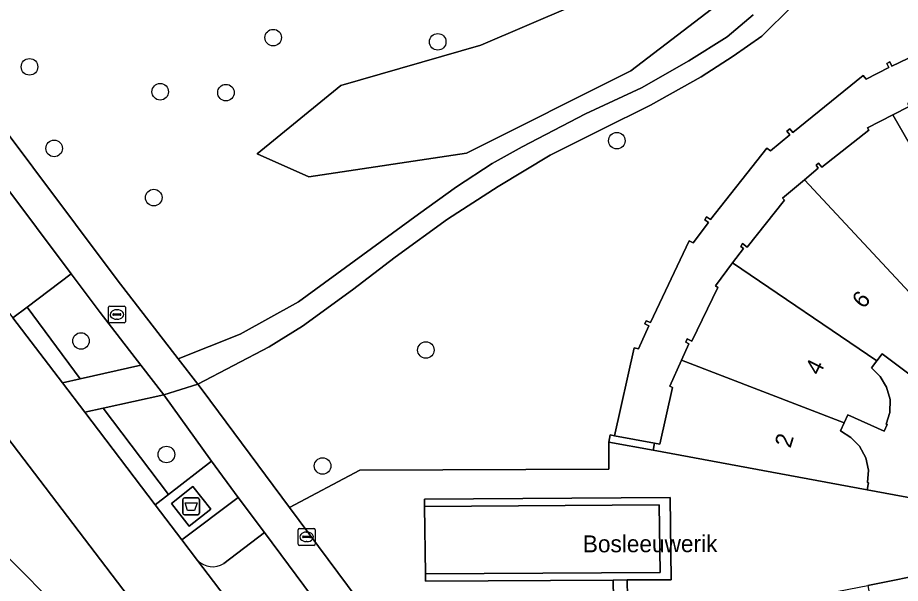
# Model space of a CAD drawing. Extents: x 156661 to 157576, y 383570 to 384425.
# Drawn here: x 156984.6 to 157036.8, y 384097.3 to 384130.7 of the extents above; entities that cross this region are included whole.
import ezdxf

# ---------------------------------------------------------------- set-up
doc = ezdxf.new("R2010")
doc.units = 0
for name, color, linetype in [('IMGEO_Afval_apart_plaats', 7, 'Continuous'), ('IMGEO_Berm_groen', 7, 'Continuous'), ('IMGEO_Berm_open', 7, 'Continuous'), ('IMGEO_Boom', 7, 'Continuous'), ('IMGEO_Brandkraan', 7, 'Continuous'), ('IMGEO_Erf', 7, 'Continuous'), ('IMGEO_Fietspad_gesloten', 7, 'Continuous'), ('IMGEO_Greppel_droge_sloot', 7, 'Continuous'), ('IMGEO_Groenvoorziening', 7, 'Continuous'), ('IMGEO_Kolk', 7, 'Continuous'), ('IMGEO_Muur', 7, 'Continuous'), ('IMGEO_Openbare_ruimte_label', 7, 'Continuous'), ('IMGEO_Pand', 7, 'Continuous'), ('IMGEO_Pand_nummerreeks', 7, 'Continuous'), ('IMGEO_Parkeervlak_open', 7, 'Continuous'), ('IMGEO_Rijbaan_lokaal_gesloten', 7, 'Continuous'), ('IMGEO_Rijbaan_lokaal_open', 7, 'Continuous'), ('IMGEO_Voetpad_gesloten', 7, 'Continuous'), ('IMGEO_Voetpad_halfverhard', 7, 'Continuous'), ('IMGEO_Voetpad_open', 7, 'Continuous')]:
    doc.layers.add(name, color=color, linetype=linetype)

msp = doc.modelspace()

# ---------------------------------------------------------------- linework, layer by layer
at = {"layer": 'IMGEO_Afval_apart_plaats'}
for p, q in [((156994.354, 384101.414), (156994.354, 384102.214)), ((156994.354, 384102.214), (156994.354, 384101.414)), ((156994.454, 384102.314), (156995.244, 384102.314)), ((156995.244, 384102.314), (156994.454, 384102.314)), ((156995.344, 384102.214), (156995.344, 384101.414)), ((156995.344, 384101.414), (156995.344, 384102.214)), ((156995.244, 384101.314), (156994.454, 384101.314)), ((156994.454, 384101.314), (156995.244, 384101.314))]:
    msp.add_line(p, q, dxfattribs=at)
msp.add_lwpolyline([(156994.497, 384102.028), (156995.201, 384102.028), (156995.052, 384101.558), (156994.646, 384101.558), (156994.497, 384102.028)], dxfattribs=at)
for centre, start, end in [((156994.454, 384102.214), 90, 180), ((156994.454, 384102.214), 90, 180), ((156995.244, 384102.214), 0, 90), ((156995.244, 384102.214), 360, 90), ((156994.454, 384101.414), 180, 270), ((156994.454, 384101.414), 180, 270), ((156995.244, 384101.414), 270, 0), ((156995.244, 384101.414), 270, 0)]:
    msp.add_arc(centre, 0.1, start, end, dxfattribs=at)
at = {"layer": 'IMGEO_Berm_groen'}
for points in [[(156989.479, 384113.271), (156987.764, 384115.552), (156985.156, 384113.579), (156988.303, 384109.35), (156991.886, 384110.152)], [(156993.23, 384108.41), (156989.647, 384107.62), (156993.506, 384102.511), (156996.047, 384104.484)]]:
    msp.add_lwpolyline(points, close=True, dxfattribs=at)
msp.add_lwpolyline([(156991.93, 384090.278), (156994.406, 384092.206), (156983.642, 384106.325)], dxfattribs=at)
msp.add_arc((156891.837, 384005.355), 131.265, 40.31264, 47.88862, dxfattribs=at)
at = {"layer": 'IMGEO_Berm_open'}
for points in [[(156985.156, 384113.579), (156984.323, 384112.949), (156987.249, 384109.103), (156988.303, 384109.35)], [(156989.647, 384107.62), (156988.566, 384107.372), (156992.723, 384101.907), (156993.506, 384102.511)]]:
    msp.add_lwpolyline(points, close=True, dxfattribs=at)
at = {"layer": 'IMGEO_Boom'}
for centre in [(156999.703, 384129.513), (157009.428, 384129.265), (156985.299, 384127.786), (156993.025, 384126.315), (156996.911, 384126.263), (157020.016, 384123.422), (156986.756, 384122.965), (156992.644, 384120.061), (156988.345, 384111.588), (157008.728, 384111.051), (156993.392, 384104.878), (157002.623, 384104.198)]:
    msp.add_circle(centre, 0.489, dxfattribs=at)
at = {"layer": 'IMGEO_Brandkraan'}
for p, q in [((156990.039, 384113.651), (156990.891, 384113.651)), ((156989.964, 384112.725), (156989.964, 384113.577)), ((156990.223, 384113.145), (156990.223, 384113.157)), ((156990.661, 384113.108), (156990.263, 384113.108)), ((156990.266, 384113.194), (156990.664, 384113.194)), ((156990.452, 384113.431), (156990.477, 384113.431)), ((156990.707, 384113.157), (156990.707, 384113.145)), ((156990.965, 384113.577), (156990.965, 384112.725)), ((156990.891, 384112.651), (156990.039, 384112.651)), ((156990.475, 384112.871), (156990.45, 384112.871))]:
    msp.add_line(p, q, dxfattribs=at)
for points in [[(156990.039, 384113.651), (156990.891, 384113.651)], [(156989.964, 384112.725), (156989.964, 384113.577)], [(156990.965, 384113.577), (156990.965, 384112.725)], [(156990.891, 384112.651), (156990.039, 384112.651)]]:
    msp.add_lwpolyline(points, dxfattribs=at)
for centre, radius, start, end in [((156990.041, 384113.575), 0.0765, 91.552, 178.448), ((156990.041, 384113.575), 0.0765, 91.552, 178.448), ((156990.889, 384113.575), 0.0765, 1.552, 88.448), ((156990.889, 384113.575), 0.0765, 1.552, 88.448), ((156990.263, 384113.154), 0.0403, 85.8775, 175.7526), ((156990.26, 384113.144), 0.0366, 178.938, 274.7102), ((156990.664, 384113.151), 0.043, 264.8664, 352.4533), ((156990.668, 384113.156), 0.0386, 1.7309, 96.639), ((156990.041, 384112.727), 0.0765, 181.552, 268.448), ((156990.041, 384112.727), 0.0765, 181.552, 268.448), ((156990.889, 384112.727), 0.0765, 271.552, 358.448), ((156990.889, 384112.727), 0.0765, 271.552, 358.448)]:
    msp.add_arc(centre, radius, start, end, dxfattribs=at)
for centre, major_axis, ratio, start_param, end_param in [((156990.451, 384113.151), (-0.387, 0.002), 0.722429, 4.712389, 7.853982), ((156990.476, 384113.151), (-0.39, 0.002), 0.717154, 1.570796, 4.712389)]:
    msp.add_ellipse(centre, major_axis=major_axis, ratio=ratio, start_param=start_param, end_param=end_param, dxfattribs=at)
at = {"layer": 'IMGEO_Erf'}
for points in [[(157041.118, 384130.156), (157036.279, 384127.836), (157036.154, 384128.079), (157035.969, 384127.983), (157036.093, 384127.743), (157034.746, 384127.057), (157034.572, 384127.271), (157030.415, 384123.905), (157030.234, 384124.118), (157030.072, 384123.98), (157030.247, 384123.775), (157029.094, 384122.813), (157028.877, 384122.984), (157025.551, 384118.755), (157025.324, 384118.924), (157025.217, 384118.753), (157025.434, 384118.592), (157024.534, 384117.386), (157024.285, 384117.503), (157022.003, 384112.671), (157021.75, 384112.785), (157021.666, 384112.595), (157021.913, 384112.485), (157021.294, 384111.118), (157021.03, 384111.176), (157019.882, 384105.99), (157022.239, 384105.555), (157022.552, 384105.497), (157023.303, 384108.845), (157023.154, 384108.912), (157023.841, 384110.452), (157024.273, 384111.42), (157024.086, 384111.515), (157024.163, 384111.705), (157024.455, 384111.565), (157025.984, 384114.749), (157025.846, 384114.853), (157026.859, 384116.199), (157027.498, 384117.048), (157027.336, 384117.178), (157027.45, 384117.345), (157027.713, 384117.136), (157029.919, 384119.902), (157029.814, 384120.027), (157031.102, 384121.115), (157031.914, 384121.8), (157031.788, 384121.968), (157031.944, 384122.1), (157032.139, 384121.853), (157034.906, 384124.041), (157034.832, 384124.186), (157036.336, 384124.956), (157037.285, 384125.441)], [(157037.593, 384109.417), (157035.706, 384110.832), (157035.386, 384110.419), (157035.065, 384110.006), (157035.581, 384109.483), (157035.958, 384108.858), (157036.172, 384108.119), (157036.157, 384107.369), (157035.944, 384106.666), (157035.999, 384106.642), (157035.824, 384106.264), (157033.667, 384107.221), (157033.449, 384106.75), (157033.23, 384106.279), (157033.85, 384105.885), (157034.357, 384105.36), (157034.731, 384104.688), (157034.884, 384103.953), (157034.834, 384103.221), (157034.893, 384103.21), (157034.816, 384102.793), (157038.761, 384102.061)], [(157038.769, 384097.919), (157034.843, 384097.129), (157034.935, 384096.708), (157032.618, 384096.262), (157032.798, 384095.24), (157033.532, 384095.27), (157034.248, 384095.129), (157034.939, 384094.79), (157035.484, 384094.275), (157035.862, 384093.645), (157035.916, 384093.67), (157036.091, 384093.284), (157033.933, 384092.33), (157034.144, 384091.831), (157034.354, 384091.332), (157035.063, 384091.526), (157035.792, 384091.548), (157036.541, 384091.373), (157037.189, 384090.993)]]:
    msp.add_lwpolyline(points, dxfattribs=at)
at = {"layer": 'IMGEO_Fietspad_gesloten'}
msp.add_arc((156891.837, 384005.355), 131.265, 40.31264, 47.88862, dxfattribs=at)
at = {"layer": 'IMGEO_Greppel_droge_sloot'}
msp.add_lwpolyline([(157020.852, 384127.544), (157028.032, 384133.073), (157030.878, 384136.293), (157029.595, 384139.138), (157020.136, 384132.567), (157011.975, 384129.074), (157003.697, 384126.69), (156998.763, 384122.638), (157001.811, 384121.29), (157011.124, 384122.683)], close=True, dxfattribs=at)
at = {"layer": 'IMGEO_Groenvoorziening'}
for points in [[(156960.044, 384155.717), (156983.009, 384125.143), (156990.473, 384115.206), (156994.084, 384110.528), (156997.761, 384111.981), (157001.193, 384113.9), (157008.294, 384119.078), (157010.532, 384120.698), (157012.649, 384122.072), (157014.412, 384123.063), (157018.159, 384125.008), (157021.465, 384126.549), (157024.262, 384128.135), (157026.54, 384129.566), (157028.082, 384130.851)], [(157030.382, 384131.364), (157028.584, 384129.591), (157026.896, 384128.424), (157025.001, 384127.192), (157022.013, 384125.527), (157019.077, 384124.071), (157016.072, 384122.571), (157012.993, 384120.722), (157010.012, 384118.789), (157006.916, 384116.533), (157004.398, 384114.6), (157001.439, 384112.453), (156999.469, 384111.238), (156995.242, 384109.027), (156995.502, 384108.69), (157000.672, 384101.738), (157004.825, 384103.959), (157019.552, 384104.012), (157019.547, 384105.61), (157019.616, 384106.039), (157019.882, 384105.99), (157021.03, 384111.176), (157021.294, 384111.118), (157021.913, 384112.485), (157021.666, 384112.595), (157021.75, 384112.785), (157022.003, 384112.671), (157024.285, 384117.503), (157024.534, 384117.386), (157025.434, 384118.592), (157025.217, 384118.753), (157025.324, 384118.924), (157025.551, 384118.755), (157028.877, 384122.984), (157029.094, 384122.813), (157030.247, 384123.775), (157030.072, 384123.98), (157030.234, 384124.118), (157030.415, 384123.905), (157034.572, 384127.271), (157034.746, 384127.057), (157036.093, 384127.743), (157035.969, 384127.983), (157036.154, 384128.079), (157036.279, 384127.836), (157041.118, 384130.156)]]:
    msp.add_lwpolyline(points, dxfattribs=at)
msp.add_lwpolyline([(157029.595, 384139.138), (157030.878, 384136.293), (157028.032, 384133.073), (157020.852, 384127.544), (157011.124, 384122.683), (157001.811, 384121.29), (156998.763, 384122.638), (157003.697, 384126.69), (157011.975, 384129.074), (157020.136, 384132.567)], close=True, dxfattribs=at)
at = {"layer": 'IMGEO_Kolk'}
for p, q in [((157001.176, 384099.582), (157001.176, 384100.434)), ((157001.251, 384100.508), (157002.103, 384100.508)), ((157001.478, 384100.051), (157001.876, 384100.051)), ((157001.664, 384100.288), (157001.689, 384100.288)), ((157002.177, 384100.434), (157002.177, 384099.582)), ((157002.103, 384099.508), (157001.251, 384099.508)), ((157001.435, 384100.002), (157001.435, 384100.014)), ((157001.873, 384099.965), (157001.475, 384099.965)), ((157001.687, 384099.728), (157001.662, 384099.728)), ((157001.919, 384100.014), (157001.919, 384100.002))]:
    msp.add_line(p, q, dxfattribs=at)
for points in [[(157001.176, 384099.582), (157001.176, 384100.434)], [(157001.251, 384100.508), (157002.103, 384100.508)], [(157002.177, 384100.434), (157002.177, 384099.582)], [(157002.103, 384099.508), (157001.251, 384099.508)]]:
    msp.add_lwpolyline(points, dxfattribs=at)
for centre, radius, start, end in [((157001.253, 384100.432), 0.0765, 91.552, 178.448), ((157001.253, 384100.432), 0.0765, 91.552, 178.448), ((157001.475, 384100.011), 0.0403, 85.8775, 175.7526), ((157001.88, 384100.013), 0.0386, 1.7309, 96.639), ((157002.101, 384100.432), 0.0765, 1.552, 88.448), ((157002.101, 384100.432), 0.0765, 1.552, 88.448), ((157001.253, 384099.584), 0.0765, 181.552, 268.448), ((157001.253, 384099.584), 0.0765, 181.552, 268.448), ((157001.472, 384100.001), 0.0366, 178.938, 274.7102), ((157001.876, 384100.008), 0.043, 264.8664, 352.4533), ((157002.101, 384099.584), 0.0765, 271.552, 358.448), ((157002.101, 384099.584), 0.0765, 271.552, 358.448)]:
    msp.add_arc(centre, radius, start, end, dxfattribs=at)
for centre, major_axis, ratio, start_param, end_param in [((157001.663, 384100.008), (-0.387, 0.002), 0.722429, 4.712389, 7.853982), ((157001.688, 384100.008), (-0.39, 0.002), 0.717154, 1.570796, 4.712389)]:
    msp.add_ellipse(centre, major_axis=major_axis, ratio=ratio, start_param=start_param, end_param=end_param, dxfattribs=at)
at = {"layer": 'IMGEO_Muur'}
for points in [[(157019.882, 384105.99), (157019.616, 384106.039), (157019.547, 384105.61), (157022.161, 384105.134), (157022.239, 384105.555)], [(157020.634, 384097.464), (157023.227, 384097.478), (157023.17, 384102.337), (157008.649, 384102.241), (157008.652, 384101.811), (157022.525, 384101.903), (157022.572, 384097.905), (157008.697, 384097.827), (157008.7, 384097.397), (157019.801, 384097.459)]]:
    msp.add_lwpolyline(points, close=True, dxfattribs=at)
at = {"layer": 'IMGEO_Pand'}
for points in [[(157042.322, 384127.458), (157040.67, 384127.096), (157040.705, 384126.94), (157037.52, 384125.433), (157037.375, 384125.722), (157037.192, 384125.629), (157037.285, 384125.441), (157036.336, 384124.956), (157041.479, 384116.024), (157041.945, 384116.251), (157043.012, 384114.146), (157043.389, 384114.342), (157043.361, 384114.395), (157043.97, 384114.805), (157044.455, 384115.378), (157044.755, 384116.087), (157044.858, 384116.808), (157044.788, 384117.54), (157045.3, 384117.659)], [(157031.102, 384121.115), (157038.119, 384113.575), (157038.527, 384113.904), (157040.038, 384112.093), (157040.361, 384112.367), (157040.322, 384112.413), (157040.824, 384112.949), (157041.169, 384113.615), (157041.304, 384114.373), (157041.243, 384115.099), (157041.012, 384115.797), (157041.479, 384116.024), (157036.336, 384124.956), (157034.832, 384124.186), (157034.906, 384124.041), (157032.139, 384121.853), (157031.944, 384122.1), (157031.788, 384121.968), (157031.914, 384121.8)], [(157031.102, 384121.115), (157029.814, 384120.027), (157029.919, 384119.902), (157027.713, 384117.136), (157027.45, 384117.345), (157027.336, 384117.178), (157027.498, 384117.048), (157026.859, 384116.199), (157035.386, 384110.419), (157035.706, 384110.832), (157037.593, 384109.417), (157037.847, 384109.757), (157037.799, 384109.793), (157038.167, 384110.428), (157038.354, 384111.155), (157038.316, 384111.924), (157038.094, 384112.618), (157037.712, 384113.246), (157038.119, 384113.575)], [(157026.859, 384116.199), (157025.846, 384114.853), (157025.984, 384114.749), (157024.455, 384111.565), (157024.163, 384111.705), (157024.086, 384111.515), (157024.273, 384111.42), (157023.841, 384110.452), (157033.449, 384106.75), (157033.667, 384107.221), (157035.824, 384106.264), (157035.999, 384106.642), (157035.944, 384106.666), (157036.157, 384107.369), (157036.172, 384108.119), (157035.958, 384108.858), (157035.581, 384109.483), (157035.065, 384110.006), (157035.386, 384110.419)], [(157033.449, 384106.75), (157023.841, 384110.452), (157023.154, 384108.912), (157023.303, 384108.845), (157022.552, 384105.497), (157022.239, 384105.555), (157022.161, 384105.134), (157034.816, 384102.793), (157034.893, 384103.21), (157034.834, 384103.221), (157034.884, 384103.953), (157034.731, 384104.688), (157034.357, 384105.36), (157033.85, 384105.885), (157033.23, 384106.279)]]:
    msp.add_lwpolyline(points, close=True, dxfattribs=at)
at = {"layer": 'IMGEO_Parkeervlak_open'}
msp.add_lwpolyline([(156981.529, 384123.845), (156978.024, 384121.227), (156978.939, 384120.025), (156984.323, 384112.949), (156985.156, 384113.579), (156987.764, 384115.552)], close=True, dxfattribs=at)
for points in [[(156999.181, 384100.275), (156997.641, 384102.344), (156994.299, 384099.836), (156995.236, 384098.62)], [(156996.777, 384098.435), (156999.181, 384100.275)]]:
    msp.add_lwpolyline(points, dxfattribs=at)
msp.add_arc((156996.121, 384099.485), 1.238, 224.3341, 301.9745, dxfattribs=at)
at = {"layer": 'IMGEO_Rijbaan_lokaal_gesloten'}
msp.add_lwpolyline([(157022.525, 384101.903), (157008.652, 384101.811), (157008.697, 384097.827), (157022.572, 384097.905)], close=True, dxfattribs=at)
at = {"layer": 'IMGEO_Rijbaan_lokaal_open'}
for points in [[(157042.601, 384036.329), (157033.137, 384048.791), (157025.037, 384059.437), (157021.082, 384064.634), (157019.642, 384066.527), (157017.934, 384068.772), (157016.726, 384070.36), (157002.783, 384088.679), (156999.757, 384092.656), (156995.236, 384098.62), (156994.299, 384099.836), (156992.723, 384101.907), (156988.566, 384107.372), (156987.249, 384109.103), (156984.323, 384112.949)], [(156983.642, 384106.325), (156994.406, 384092.206), (156995.355, 384090.962), (157013.176, 384067.588), (157014.424, 384065.95), (157020.102, 384058.503), (157022.83, 384054.925), (157062.167, 384003.14)], [(156999.181, 384100.275), (156996.777, 384098.435)], [(157000.15, 384094.105), (157000.853, 384094.63), (157002.48, 384095.843), (156999.181, 384100.275)], [(156995.236, 384098.62), (156999.757, 384092.656)]]:
    msp.add_lwpolyline(points, dxfattribs=at)
msp.add_arc((156996.121, 384099.485), 1.238, 224.3341, 301.9745, dxfattribs=at)
at = {"layer": 'IMGEO_Voetpad_gesloten'}
for points in [[(156994.957, 384102.983), (156993.687, 384101.98), (156994.741, 384100.646), (156996.011, 384101.649)], [(157019.862, 384094.236), (157020.693, 384094.396), (157020.634, 384097.464), (157019.801, 384097.459)]]:
    msp.add_lwpolyline(points, close=True, dxfattribs=at)
at = {"layer": 'IMGEO_Voetpad_halfverhard'}
msp.add_lwpolyline([(157028.082, 384130.851), (157026.54, 384129.566), (157024.262, 384128.135), (157021.465, 384126.549), (157018.159, 384125.008), (157014.412, 384123.063), (157012.649, 384122.072), (157010.532, 384120.698), (157008.294, 384119.078), (157001.193, 384113.9), (156997.761, 384111.981), (156994.084, 384110.528), (156995.242, 384109.027), (156999.469, 384111.238), (157001.439, 384112.453), (157004.398, 384114.6), (157006.916, 384116.533), (157010.012, 384118.789), (157012.993, 384120.722), (157016.072, 384122.571), (157019.077, 384124.071), (157022.013, 384125.527), (157025.001, 384127.192), (157026.896, 384128.424), (157028.584, 384129.591), (157030.382, 384131.364)], dxfattribs=at)
at = {"layer": 'IMGEO_Voetpad_open'}
for points in [[(156972.116, 384136.364), (156979.61, 384126.397), (156981.382, 384124.041), (156981.529, 384123.845), (156987.764, 384115.552), (156989.479, 384113.271), (156991.886, 384110.152), (156993.23, 384108.41), (156995.242, 384109.027), (156994.084, 384110.528), (156990.473, 384115.206), (156983.009, 384125.143), (156960.044, 384155.717)], [(157006.39, 384094.063), (157000.672, 384101.738), (156995.502, 384108.69), (156995.242, 384109.027), (156993.23, 384108.41), (156996.047, 384104.484), (156997.641, 384102.344), (156999.181, 384100.275), (157002.48, 384095.843)], [(157038.761, 384102.061), (157034.816, 384102.793), (157022.161, 384105.134), (157019.547, 384105.61), (157019.552, 384104.012), (157004.825, 384103.959), (157000.672, 384101.738), (157006.39, 384094.063), (157019.622, 384094.19), (157019.862, 384094.236), (157019.801, 384097.459), (157008.7, 384097.397), (157008.697, 384097.827), (157008.652, 384101.811), (157008.649, 384102.241), (157023.17, 384102.337), (157023.227, 384097.478), (157020.634, 384097.464), (157020.693, 384094.396), (157022.222, 384094.691), (157034.843, 384097.129), (157038.769, 384097.919)]]:
    msp.add_lwpolyline(points, dxfattribs=at)
for points in [[(156988.566, 384107.372), (156989.647, 384107.62), (156993.23, 384108.41), (156991.886, 384110.152), (156988.303, 384109.35), (156987.249, 384109.103)], [(156996.047, 384104.484), (156993.506, 384102.511), (156992.723, 384101.907), (156994.299, 384099.836), (156997.641, 384102.344)], [(156996.011, 384101.649), (156994.741, 384100.646), (156993.687, 384101.98), (156994.957, 384102.983)]]:
    msp.add_lwpolyline(points, close=True, dxfattribs=at)

# ---------------------------------------------------------------- texts
at = {"layer": 'IMGEO_Openbare_ruimte_label'}
msp.add_text('Bosleeuwerik', height=1, rotation=0.1146, dxfattribs=at).set_placement((157018.006, 384099.095))
at = {"layer": 'IMGEO_Pand_nummerreeks'}
for s, rotation, p in [('6', 50.2712, (157034.597, 384113.441)), ('4', 63.3361, (157031.992, 384109.502)), ('2', 73.1848, (157030.276, 384105.214))]:
    msp.add_text(s, height=1, rotation=rotation, dxfattribs=at).set_placement(p)

doc.saveas('drawing.dxf')
